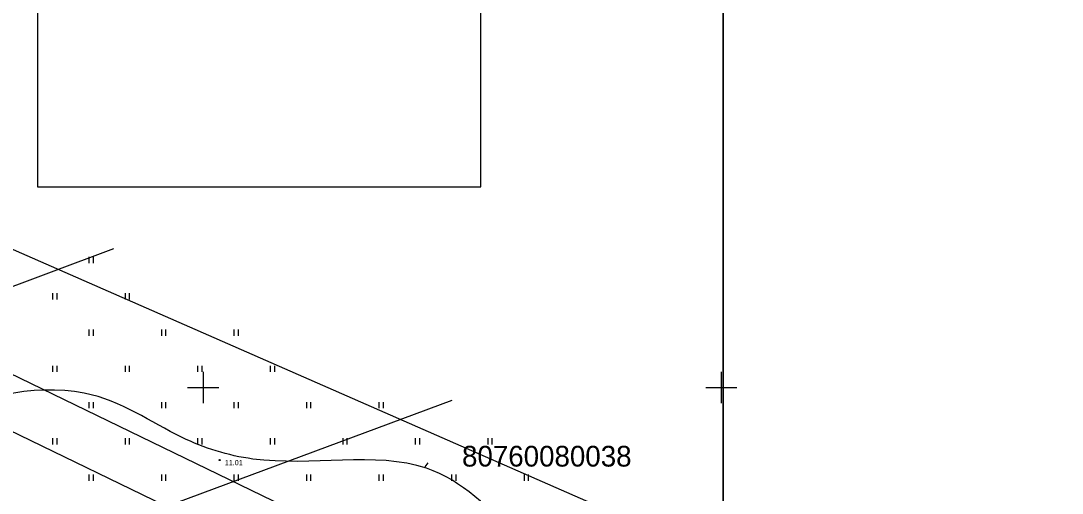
# Model space of a CAD drawing. Extents: x 503353 to 504004, y 304662 to 305049.
# Drawn here: x 503482.4 to 503582.9, y 304939.8 to 304985.4 of the extents above; entities that cross this region are included whole.
import ezdxf

# ---------------------------------------------------------------- set-up
doc = ezdxf.new("R2010")
doc.units = 0
for name, color, linetype in [('25', 7, 'Continuous'), ('59', 7, 'Continuous'), ('APGR_ELEM_####_####_#', 7, 'Continuous'), ('DREN_VADP_####_####_#', 7, 'Continuous'), ('DREN_VADP_KLKT_####_#', 7, 'Continuous'), ('GEOD_ELEM_####_####_#', 7, 'Continuous'), ('RAMI_PLAN_####_TKST_#', 7, 'Continuous'), ('RAMI_UZMR_####_####_#', 7, 'Continuous'), ('RELJ_AATZ_####_TKST_#', 7, 'Continuous'), ('RELJ_ELEM_####_####_#', 7, 'Continuous'), ('RELJ_HORZ_PAMT_####_#', 7, 'Continuous'), ('TERT_ELEM_####_####_#', 7, 'Continuous')]:
    doc.layers.add(name, color=color, linetype=linetype)

msp = doc.modelspace()

# ---------------------------------------------------------------- linework, layer by layer
at = {"layer": '25'}
msp.add_line((503595.59, 304890.48), (503425.18, 304973.04), dxfattribs=at)
at = {"layer": 'APGR_ELEM_####_####_#'}
msp.add_line((503412.34, 304984.81), (503586.7, 304900.35), dxfattribs=at)
at = {"layer": 'DREN_VADP_####_####_#'}
msp.add_line((503524.01, 304948.73), (503473.44, 304930), dxfattribs=at)
at = {"layer": 'DREN_VADP_KLKT_####_#'}
msp.add_lwpolyline([(503441.16, 304944.64), (503491.39, 304963.41)], dxfattribs=at)
at = {"layer": 'GEOD_ELEM_####_####_#'}
for p, q in [((503500, 304951.5), (503500, 304950)), ((503550, 304951.5), (503550, 304950)), ((503498.5, 304950), (503500, 304950)), ((503500, 304950), (503500, 304948.5)), ((503500, 304950), (503501.5, 304950)), ((503548.5, 304950), (503550, 304950)), ((503550, 304950), (503550, 304948.5)), ((503550, 304950), (503551.5, 304950))]:
    msp.add_line(p, q, dxfattribs=at)
at = {"layer": 'RAMI_PLAN_####_TKST_#'}
for points in [[(503692.78, 305049.44), (503692.78, 304852.26), (503550.18, 304852.26), (503550.18, 305049.44)], [(503550.18, 304891.91), (503353, 304891.91), (503353, 305034.51), (503550.18, 305034.51)], [(503484, 304969.35), (503526.78, 304969.35), (503526.78, 304996.12), (503484, 304996.12)]]:
    msp.add_lwpolyline(points, close=True, dxfattribs=at)
at = {"layer": 'RAMI_UZMR_####_####_#'}
msp.add_lwpolyline([(503825.92, 304784.83), (503697.43, 304847.71), (503608.51, 304889.84), (503606.52, 304897.2), (503679.24, 304999.94), (503684.9, 305009.76), (503666.78, 305017.94), (503656.13, 304996.39), (503644.1, 304987.6), (503600.99, 304924.26), (503587.99, 304916.67), (503422.24, 304989.37), (503408.62, 305023.5), (503368.78, 305020.18)], dxfattribs=at)
at = {"layer": 'RELJ_ELEM_####_####_#'}
msp.add_circle((503501.59, 304943), 0.05, dxfattribs=at)
at = {"layer": 'RELJ_HORZ_PAMT_####_#'}
msp.add_line((503521.67, 304942.74), (503521.38, 304942.33), dxfattribs=at)
msp.add_spline([(503515.84, 304912.45), (503529.27, 304910.78), (503540.55, 304906.06), (503546.64, 304910.87), (503542.75, 304919.71), (503537.5, 304925.72), (503521.56, 304942.2), (503504.79, 304943.1), (503497.96, 304945.18), (503488.51, 304949.45), (503475.43, 304946.23), (503484.34, 304930.92), (503496.13, 304918.62)], degree=3, dxfattribs=at)
at = {"layer": 'TERT_ELEM_####_####_#'}
for p, q in [((503489, 304962), (503489, 304962.6)), ((503489.4, 304962), (503489.4, 304962.6)), ((503485.5, 304958.5), (503485.5, 304959.1)), ((503485.9, 304958.5), (503485.9, 304959.1)), ((503492.5, 304958.5), (503492.5, 304959.1)), ((503492.9, 304958.5), (503492.9, 304959.1)), ((503489, 304955), (503489, 304955.6)), ((503489.4, 304955), (503489.4, 304955.6)), ((503496, 304955), (503496, 304955.6)), ((503496.4, 304955), (503496.4, 304955.6)), ((503503, 304955), (503503, 304955.6)), ((503503.4, 304955), (503503.4, 304955.6)), ((503485.5, 304951.5), (503485.5, 304952.1)), ((503485.9, 304951.5), (503485.9, 304952.1)), ((503492.5, 304951.5), (503492.5, 304952.1)), ((503492.9, 304951.5), (503492.9, 304952.1)), ((503499.5, 304951.5), (503499.5, 304952.1)), ((503499.9, 304951.5), (503499.9, 304952.1)), ((503506.5, 304951.5), (503506.5, 304952.1)), ((503506.9, 304951.5), (503506.9, 304952.1)), ((503489, 304948), (503489, 304948.6)), ((503489.4, 304948), (503489.4, 304948.6)), ((503496, 304948), (503496, 304948.6)), ((503496.4, 304948), (503496.4, 304948.6)), ((503503, 304948), (503503, 304948.6)), ((503503.4, 304948), (503503.4, 304948.6)), ((503510, 304948), (503510, 304948.6)), ((503510.4, 304948), (503510.4, 304948.6)), ((503517, 304948), (503517, 304948.6)), ((503517.4, 304948), (503517.4, 304948.6)), ((503485.5, 304944.5), (503485.5, 304945.1)), ((503485.9, 304944.5), (503485.9, 304945.1)), ((503492.5, 304944.5), (503492.5, 304945.1)), ((503492.9, 304944.5), (503492.9, 304945.1)), ((503499.5, 304944.5), (503499.5, 304945.1)), ((503499.9, 304944.5), (503499.9, 304945.1)), ((503506.5, 304944.5), (503506.5, 304945.1)), ((503506.9, 304944.5), (503506.9, 304945.1)), ((503513.5, 304944.5), (503513.5, 304945.1)), ((503513.9, 304944.5), (503513.9, 304945.1)), ((503520.5, 304944.5), (503520.5, 304945.1)), ((503520.9, 304944.5), (503520.9, 304945.1)), ((503527.5, 304944.5), (503527.5, 304945.1)), ((503527.9, 304944.5), (503527.9, 304945.1)), ((503489, 304941), (503489, 304941.6)), ((503489.4, 304941), (503489.4, 304941.6)), ((503496, 304941), (503496, 304941.6)), ((503496.4, 304941), (503496.4, 304941.6)), ((503503, 304941), (503503, 304941.6)), ((503503.4, 304941), (503503.4, 304941.6)), ((503510, 304941), (503510, 304941.6)), ((503510.4, 304941), (503510.4, 304941.6)), ((503517, 304941), (503517, 304941.6)), ((503517.4, 304941), (503517.4, 304941.6)), ((503524, 304941), (503524, 304941.6)), ((503524.4, 304941), (503524.4, 304941.6)), ((503531, 304941), (503531, 304941.6)), ((503531.4, 304941), (503531.4, 304941.6))]:
    msp.add_line(p, q, dxfattribs=at)

# ---------------------------------------------------------------- texts
at = {"layer": '59'}
msp.add_text('80760080038', height=2, dxfattribs=at).set_placement((503524.98, 304942.37))
at = {"layer": 'RELJ_AATZ_####_TKST_#'}
msp.add_text('11.01', height=0.5, dxfattribs=at).set_placement((503502.09, 304942.5))

doc.saveas('drawing.dxf')
